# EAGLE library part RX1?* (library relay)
SMALL MICRO WAVE RELAY NAiS Source: http://www.mew-europe.com/.. en_ds_61307_0000.pdf
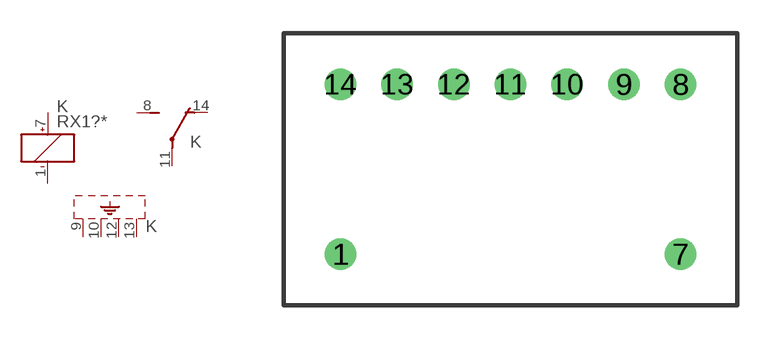
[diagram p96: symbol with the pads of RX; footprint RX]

Designator prefix K; gates 1=K+- 2=U 3=SHIELD-4

## RX1000H (OC_FARNELL: unknown; OC_NEWARK: unknown), RX10003 (OC_FARNELL: unknown; OC_NEWARK: unknown), RX1004H (OC_FARNELL: unknown; OC_NEWARK: unknown), RX10006 (OC_FARNELL: unknown; OC_NEWARK: unknown), RX10012 (OC_FARNELL: unknown; OC_NEWARK: unknown), RX10024 (OC_FARNELL: unknown; OC_NEWARK: unknown)  [RX]
1  1:-  pas
7  1:+  pas
8  2:S  pas
9  3:SH  pas
10  3:SH  pas
11  2:P  pas
12  3:SH  pas
13  3:SH  pas
14  2:O  pas

## RX11003 (OC_FARNELL: unknown; OC_NEWARK: unknown), RX1104H (OC_FARNELL: unknown; OC_NEWARK: unknown), RX11006 (OC_FARNELL: unknown; OC_NEWARK: unknown), RX11009 (OC_FARNELL: unknown; OC_NEWARK: unknown), RX11012 (OC_FARNELL: unknown; OC_NEWARK: unknown), RX11024 (OC_FARNELL: unknown; OC_NEWARK: unknown)  [RX]
1  1:+  pas
7  1:-  pas
8  2:S  pas
9  3:SH  pas
10  3:SH  pas
11  2:P  pas
12  3:SH  pas
13  3:SH  pas
14  2:O  pas

## Footprint RX (pad centres in mm)
SMALL MICRO WAVE RELAY NAiS Source: http://www.mew-europe.com/.. en_ds_61307_0000.pdf
drill 0.9 round: 1 -7.62,-3.81; 7 7.62,-3.81; 8 7.62,3.81; 9 5.08,3.81; 10 2.54,3.81; 11 0,3.81; 12 -2.54,3.81; 13 -5.08,3.81; 14 -7.62,3.81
